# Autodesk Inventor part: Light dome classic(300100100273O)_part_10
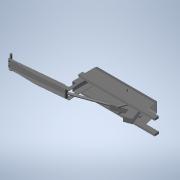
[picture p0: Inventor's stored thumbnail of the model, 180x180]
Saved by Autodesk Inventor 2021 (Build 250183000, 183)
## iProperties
Created: 2026-04
Part Number: Light dome classic(300100100273O)_part_10
Material: Generic
Catalog Web Link: www.3dfindit.com
Description: Light dome classic_part_10-
Vendor: KINGSPAN
Document SubType Name: Modeling
Designer: psAdmin
Manufacturer: KINGSPAN
Mass: 4026.95 g
Surface Area: 11889 cm^2
Volume: 4026.95 cm^3
Density: 1 g/cm^3
Appearance: PSOLRGB-255-255-255
Category: PARTsolutions
Company: KINGSPAN
Title: Light dome classic(300100100273O)_part_10
Author: Cadenas PARTsolutions
PSOL_IDENT_0: {$CADENAS_DATA/23d-libs/kingspan_kla/light_dome_classic/parts/part_10.prj},267 {VTYP=3D},{NB=Light d
PSOL_IDENT_1: ome classic(300100100273O)_part_10},{LINA=Light dome classic(300100100273O)_part_10},{NN=Light dome
PSOL_IDENT_2: classic_part_10},{DATE=15.07.2024 10:56:11},{GEOMDATE=03.07.2024 08:17:00},{VERSION=},{LINEID=10},{W
PSOL_IDENT_3: BVAR=LODLEVEL,L,W,DP,OP,BA,OC},{WBNUMERIC=W}  {NB=Light dome classic(300100100273O)_part_10},{LINA=L
PSOL_IDENT_4: ight dome classic(300100100273O)_part_10},{KT=DUMMY},{IDNR=},{PN=Light dome classic},{LODLEVEL=300},
PSOL_IDENT_5: {L=100},{W=100},{DRIVE=1},{WX=100,150,200,250,300},{DP=2},{OP=7},{BA=3},{OC=O},{OPX='7','24/48 V OPE
PSOL_IDENT_6: N/CLOSE including ventilation function'},{LX=1000},{XWX=1000},{HEI=1048.274},{VER=3},{DPX='1', 'Natu
PSOL_IDENT_7: ral ventilation', '2'  , 'NSHEV (natural smoke, heat exhaust ventilation)', '3', 'Fixed','4','NSHE'}
NB: Light dome classic(300100100273O)_part_10
NN: Light dome classic_part_10
NBSYN: $PN.($LODLEVEL.$L.$W.$DP.$OP.$BA.$OC.)_part_10
LINA: Light dome classic(300100100273O)_part_10
CATALOG: Light + Air
PN: Light dome classic
LODLEVEL: 300
L: 100
W: 100
DP: NSHEV (natural smoke, heat exhaust ventilation)
OP: 24/48 V OPEN/CLOSE including ventilation function
BA: PVC base 50 cm
OC: Open
SUPPLIER: KINGSPAN
ARTICLENO: Light dome classic(300100100273O)_part_10
BOMINFO: Light dome classic(300100100273O)_part_10
CREATOR: CADENAS GmbH
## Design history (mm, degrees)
sketch "Sketch_2"
  geometry: L1 (-392.358, -234.9)-(417.255, -234.9); L2 (417.255, -234.9)-(417.255, -191); L3 (417.255, -191)-(-392.358, -191); L4 (-392.358, -191)-(-392.358, -234.9)
  constraints: 8 end point
extrude "Extrusion1" join sketch "Sketch_2" distance "d0" = 23; taper "d1" = 0 deg
sketch "Sketch_5"
  geometry: L1 (-118, -119.6)-(-112.169, -149.6); L2 (-112.169, -149.6)-(-5.831, -149.6); L3 (-5.831, -149.6)-(0, -119.6); L4 (0, -119.6)-(0, 2); L5 (0, 2)-(-2, 2); L6 (-2, 2)-(-2, -119.6); L7 (-2, -119.6)-(-7.443, -147.6); L8 (-7.443, -147.6)-(-110.557, -147.6); L9 (-110.557, -147.6)-(-116, -119.6); L10 (-116, -119.6)-(-116, 2); L11 (-116, 2)-(-118, 2); L12 (-118, 2)-(-118, -119.6)
  constraints: 24 end point
extrude "Extrusion2" join sketch "Sketch_5" distance "d2" = 1000; taper "d3" = 0 deg
sketch "Sketch_6"
  geometry: L1 (-892.358, -254.9)-(437.255, -254.9); L2 (437.255, -254.9)-(437.255, 220); L3 (437.255, 220)-(-892.358, 220); L4 (-892.358, 220)-(-892.358, -254.9); L5 (-392.358, 200)-(-392.358, -234.9); L6 (-392.358, -234.9)-(417.255, -234.9); L7 (417.255, -234.9)-(417.255, -193); L8 (417.255, -193)-(271.255, -193); L9 (271.255, -193)-(165.951, 200); L10 (165.951, 200)-(-392.358, 200)
  constraints: 20 end point
extrude "Extrusion3" cut sketch "Sketch_6" stored distance "d4" = 328; taper "d5" = 0 deg
sketch "Sketch_7"
  geometry: L1 (395.358, 43.4)-(395.358, 293.4); L2 (395.358, 293.4)-(392.358, 293.4); L3 (392.358, 293.4)-(392.358, 46.4); L4 (392.358, 46.4)-(373.358, 46.4); L5 (373.358, 46.4)-(373.358, 43.4); L6 (373.358, 43.4)-(395.358, 43.4)
  constraints: 12 end point
extrude "Extrusion4" join sketch "Sketch_7" stored distance "d6" = 85; taper "d7" = 0 deg
sketch "Sketch_8"
  geometry: L1 (0, -4.5)-(57, -4.5); L2 (57, -4.5)-(57, -1.5); L3 (57, -1.5)-(3.5, -1.5); L4 (3.5, -1.5)-(3.5, 86.5); L5 (3.5, 86.5)-(57, 86.5); L6 (57, 86.5)-(57, 89.5); L7 (57, 89.5)-(0, 89.5); L8 (0, 89.5)-(0, -4.5)
  constraints: 16 end point
extrude "Extrusion5" join sketch "Sketch_8" distance "d8" = 250; taper "d9" = 0 deg
sketch "Sketch_12"
  geometry: L1 (239.913, -51.324)-(350.508, -61.973); L2 (350.508, -61.973)-(381.602, 260.956); L3 (381.602, 260.956)-(376.576, 452.899); L4 (376.576, 452.899)-(384.531, 535.517); L5 (384.531, 535.517)-(366.017, 537.299); L6 (366.017, 537.299)-(315.41, 11.73); L7 (315.41, 11.73)-(320.387, 11.251); L8 (320.387, 11.251)-(316.809, -25.909); L9 (316.809, -25.909)-(236.087, -30.676); A1 r 10.5 centre (238, -41) between (236.087, -30.676) and (239.913, -51.324)
  constraints: 18 end point, 2 point on circle, 1 centre point
extrude "Extrusion6" join sketch "Sketch_12" distance "d10" = 4; taper "d11" = 0 deg
sketch "Sketch_13"
  geometry: L1 (236.087, 30.676)-(316.809, 25.909); L2 (316.809, 25.909)-(320.387, -11.251); L3 (320.387, -11.251)-(315.41, -11.73); L4 (315.41, -11.73)-(366.017, -537.299); L5 (366.017, -537.299)-(384.531, -535.517); L6 (384.531, -535.517)-(376.576, -452.899); L7 (376.576, -452.899)-(381.602, -260.956); L8 (381.602, -260.956)-(350.508, 61.973); L9 (350.508, 61.973)-(239.913, 51.324); A1 r 10.5 centre (238, 41) between (239.913, 51.324) and (236.087, 30.676)
  constraints: 18 end point, 2 point on circle, 1 centre point
extrude "Extrusion7" join sketch "Sketch_13" distance "d12" = 4; taper "d13" = 0 deg
sketch "Sketch_15"
  geometry: L1 (0, 4)-(0, 0); L2 (0, 0)-(88, 0); L3 (88, 0)-(88, 4); L4 (88, 4)-(0, 4)
  constraints: 8 end point
extrude "Extrusion8" join sketch "Sketch_15" distance "d14" = 540; taper "d15" = 0 deg
sketch "Sketch_4"
  geometry: L1 (-392.358, -234.9)-(417.255, -234.9); L2 (417.255, -234.9)-(417.255, -191); L3 (417.255, -191)-(-392.358, -191); L4 (-392.358, -191)-(-392.358, -234.9)
  constraints: 8 end point
extrude "Extrusion9" join sketch "Sketch_4" distance "d16" = 23; taper "d17" = 0 deg
sketch "Sketch_19"
  geometry: C1 r 6 at (7.745, 113); 1 further point
  constraints: 1 centre point
extrude "Extrusion10" join sketch "Sketch_19" stored distance "d18" = 164; taper "d19" = 0 deg
sketch "Sketch_20"
  geometry: L1 (-12.131, -127.345)-(39.409, -143.102); L2 (39.409, -143.102)-(43.661, -264.849); L3 (63.052, -267.92)-(104.99, -152.695); L4 (104.99, -152.695)-(176.564, -174.578); L5 (176.564, -174.578)-(178.755, -187); L6 (208.518, -184.347)-(204.62, -162.241); L7 (204.62, -162.241)-(-3.36, -98.655); A1 r 15 centre (-7.745, -113) between (-3.36, -98.655) and (-12.131, -127.345); A2 r 10 centre (53.655, -264.5) between (43.661, -264.849) and (63.052, -267.92); A3 r 15 centre (193.755, -187) between (178.755, -187) and (208.518, -184.347)
  constraints: 14 end point, 6 point on circle, 3 centre point
extrude "Extrusion11" join sketch "Sketch_20" distance "d20" = 8; taper "d21" = 0 deg
sketch "Sketch_21"
  geometry: L1 (-12.131, -127.345)-(39.409, -143.102); L2 (39.409, -143.102)-(43.661, -264.849); L3 (63.052, -267.92)-(104.99, -152.695); L4 (104.99, -152.695)-(176.564, -174.578); L5 (176.564, -174.578)-(178.755, -187); L6 (208.518, -184.347)-(204.62, -162.241); L7 (204.62, -162.241)-(-3.36, -98.655); A1 r 15 centre (-7.745, -113) between (-3.36, -98.655) and (-12.131, -127.345); A2 r 10 centre (53.655, -264.5) between (43.661, -264.849) and (63.052, -267.92); A3 r 15 centre (193.755, -187) between (178.755, -187) and (208.518, -184.347)
  constraints: 14 end point, 6 point on circle, 3 centre point
extrude "Extrusion12" join sketch "Sketch_21" distance "d22" = 8; taper "d23" = 0 deg
sketch "Sketch_22"
  geometry: L1 (36.538, 234.788)-(16.866, 286.159); L2 (16.866, 286.159)-(-127.911, 233.598); L3 (-127.911, 233.598)-(-162.962, 325.132); L4 (-162.962, 325.132)-(-234.411, 299.193); L5 (-234.411, 299.193)-(-179.689, 156.288); L6 (-179.689, 156.288)-(36.538, 234.788)
  constraints: 12 end point
extrude "Extrusion13" join sketch "Sketch_22" stored distance "d24" = 47; taper "d25" = 0 deg
sketch "Sketch_25"
  geometry: L1 (370.978, 385.46)-(26.702, 260.473); L2 (26.702, 260.473)-(22.777, 270.724); L3 (22.777, 270.724)-(367.233, 395.776); L4 (367.233, 395.776)-(370.978, 385.46); L5 (370.978, 385.46)-(26.702, 260.473)
  constraints: 10 end point
revolve "Revolution1" sketch "Sketch_25" stored, may be unused: angle "d26" = 360 deg
sketch "Sketch_26"
  geometry: L1 (0, -40)-(0, 40); L2 (0, 40)-(17, 40); L3 (17, 40)-(17, -40); L4 (17, -40)-(0, -40); L5 (0, -40)-(0, 40)
  constraints: 10 end point
revolve "Revolution2" sketch "Sketch_26" stored, may be unused: angle "d27" = 360 deg
sketch "Sketch_27"
  geometry: C1 r 7.5 at (8, 64); 1 further point
  constraints: 1 centre point
extrude "Extrusion14" join sketch "Sketch_27" distance "d28" = 5.5; taper "d29" = 0 deg
sketch "Sketch_28"
  geometry: C1 r 5.9 at (0, 0); 1 further point
  constraints: 1 centre point
extrude "Extrusion15" join sketch "Sketch_28" distance "d30" = 4; taper "d31" = 0 deg
sketch "Sketch_29"
  geometry: C1 r 7.5 at (8, 24); 1 further point
  constraints: 1 centre point
extrude "Extrusion16" join sketch "Sketch_29" distance "d32" = 5.5; taper "d33" = 0 deg
sketch "Sketch_30"
  geometry: C1 r 5.9 at (0, 0); 1 further point
  constraints: 1 centre point
extrude "Extrusion17" join sketch "Sketch_30" distance "d34" = 4; taper "d35" = 0 deg
sketch "Sketch_31"
  geometry: C1 r 4 at (8, 64); 1 further point
  constraints: 1 centre point
extrude "Extrusion18" join sketch "Sketch_31" distance "d36" = 20.5; taper "d37" = 0 deg
sketch "Sketch_32"
  geometry: C1 r 4 at (8, 24); 1 further point
  constraints: 1 centre point
extrude "Extrusion19" join sketch "Sketch_32" distance "d38" = 20.5; taper "d39" = 0 deg
sketch "Sketch_33"
  geometry: C1 r 10 at (8, -16.5); 1 further point
  constraints: 1 centre point
extrude "Extrusion20" join sketch "Sketch_33" distance "d40" = 148; taper "d41" = 0 deg
sketch "Sketch_36"
  geometry: L1 (-401.255, 161)-(-401.255, 264.9); L2 (-401.255, 264.9)-(-422.255, 264.9); L3 (-422.255, 264.9)-(-422.255, 161); L4 (-422.255, 161)-(-401.255, 161)
  constraints: 8 end point
extrude "Extrusion21" cut sketch "Sketch_36" stored distance "d42" = 400; taper "d43" = 0 deg
node "IP_10_XY"
node "IP_10_YZ"
node "IP_10_ZX"
node "IP_10_X"
node "IP_10_Y"
node "IP_10_Z"
node "IP_10_Center"
body "Solid1"
